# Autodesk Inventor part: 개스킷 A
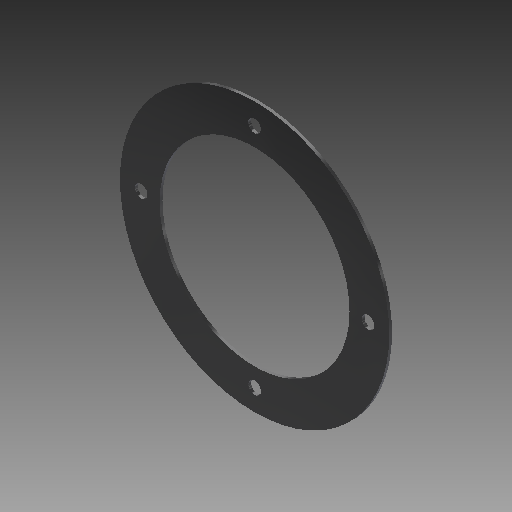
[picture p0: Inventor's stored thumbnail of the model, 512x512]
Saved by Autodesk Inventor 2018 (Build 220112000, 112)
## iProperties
Created: 2019-10
Part Number: 개스킷 A
Material: 고무
Document SubType Name: Modeling
Designer: mduedu
Density: 1 g/cm^3
Appearance: 고무 - 검은색 - 버전 1.1
Author: mduedu
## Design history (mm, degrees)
sketch "스케치1"
  geometry: C1 r 47.5 at (0, 0); C2 r 33.5 at (0, 0); 1 further point
  constraints: 2 centre point, 2 coincident
  dimensions: "d0" = 95 diameter of C1; "d1" = 67 diameter of C2
extrude "돌출1" new body sketch "스케치1" distance "d2" = 1; taper "d3" = 0 deg
sketch "스케치2" dims "d4" = 80
  geometry: C1 r 2.25 at (0, 40); 2 further points
  constraints: 2 vertical alignment, 1 centre point, 1 coincident, 2 other
  dimensions: "d5" = 4.5 diameter of C1
extrude "돌출2" cut sketch "스케치2" extent not by distance; stored distance "d6" = 1; taper "d7" = 0 deg
node "솔리드1"
pattern_circular "원형 패턴1" dims angle "d9" = 360 deg
